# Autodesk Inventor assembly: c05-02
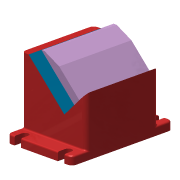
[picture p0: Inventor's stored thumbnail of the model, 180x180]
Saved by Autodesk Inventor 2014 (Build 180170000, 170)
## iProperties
Created: 2010-11
Part Number: c05-02
Document SubType Name: Assembly
Designer: Thom Tremblay
Author: Thom Tremblay
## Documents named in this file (3)
- C:\Inventor 2014 Essentials\Assemblies\Chapter 05\c05-02.iam
- C:\Inventor 2014 Essentials\Parts\Chapter 05\c05-01.ipt
- C:\Inventor 2014 Essentials\Parts\Chapter 05\c05-02.ipt
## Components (2 placed, 2 different names)
1. c05-01:1 — Mate:1, Mate:2
2. c05-02:1 — Mate:1, Mate:2
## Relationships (2: Mate 2)
- Mate:1: c05-01:1 ↔ c05-02:1
- Mate:2: c05-01:1 ↔ c05-02:1
